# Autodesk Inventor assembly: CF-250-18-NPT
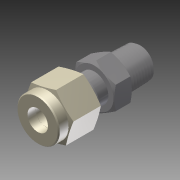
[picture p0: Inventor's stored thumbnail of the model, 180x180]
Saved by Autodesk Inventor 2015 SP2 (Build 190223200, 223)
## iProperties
Created: 2017-10
Part Number: CF-250-18-NPT
Document SubType Name: Assembly
Designer: JN
Author: JN
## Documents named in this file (5)
- C:\Users\JN\Documents\CAD Drawings\The Sensor Connection\3D\CF\CF-0250-18-NPT\3D\CF-250-18-NPT.iam
- C:\Users\JN\Documents\CAD Drawings\The Sensor Connection\3D\CF\CF-0250-18-NPT\3D\Imported Components\CF-0250-18-NPT Threaded Body\CF-0250-18-NPT Threaded Body.ipt
- C:\Users\JN\Documents\CAD Drawings\The Sensor Connection\3D\CF\CF-0250-18-NPT\3D\Imported Components\CF-0250-18-NPT Top Ferrule\CF-0250-18-NPT Top Ferrule.ipt
- C:\Users\JN\Documents\CAD Drawings\The Sensor Connection\3D\CF\CF-0250-18-NPT\3D\Imported Components\CF-0250-NPT Cap\CF-0250-NPT Cap.ipt
- C:\Users\JN\Documents\CAD Drawings\The Sensor Connection\3D\CF\CF-0250-18-NPT\3D\Imported Components\CF-0250-NPT Bottom Ferrule\CF-0250-NPT Bottom Ferrule.ipt
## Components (4 placed, 4 different names)
1. CF-0250-18-NPT Threaded Body:1 — Mate:1, Mate:8, Rotation:1
2. CF-0250-18-NPT Top Ferrule:1 — Mate:4, Mate:5, Mate:6, Mate:7
3. CF-0250-NPT Cap:1 — Mate:5, Mate:6, Rotation:1
4. CF-0250-NPT Bottom Ferrule:1 — Mate:1, Mate:4, Mate:7, Mate:8
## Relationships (7: Mate 6, RelateRotation 1)
- Mate:1: CF-0250-18-NPT Threaded Body:1 ↔ CF-0250-NPT Bottom Ferrule:1
- Mate:4: CF-0250-18-NPT Top Ferrule:1 ↔ CF-0250-NPT Bottom Ferrule:1
- Mate:5: CF-0250-18-NPT Top Ferrule:1 ↔ CF-0250-NPT Cap:1
- Mate:6: CF-0250-18-NPT Top Ferrule:1 ↔ CF-0250-NPT Cap:1
- Mate:7: CF-0250-18-NPT Top Ferrule:1 ↔ CF-0250-NPT Bottom Ferrule:1
- Mate:8: CF-0250-18-NPT Threaded Body:1 ↔ CF-0250-NPT Bottom Ferrule:1
- Rotation:1 [RelateRotation]: CF-0250-18-NPT Threaded Body:1 ↔ CF-0250-NPT Cap:1
